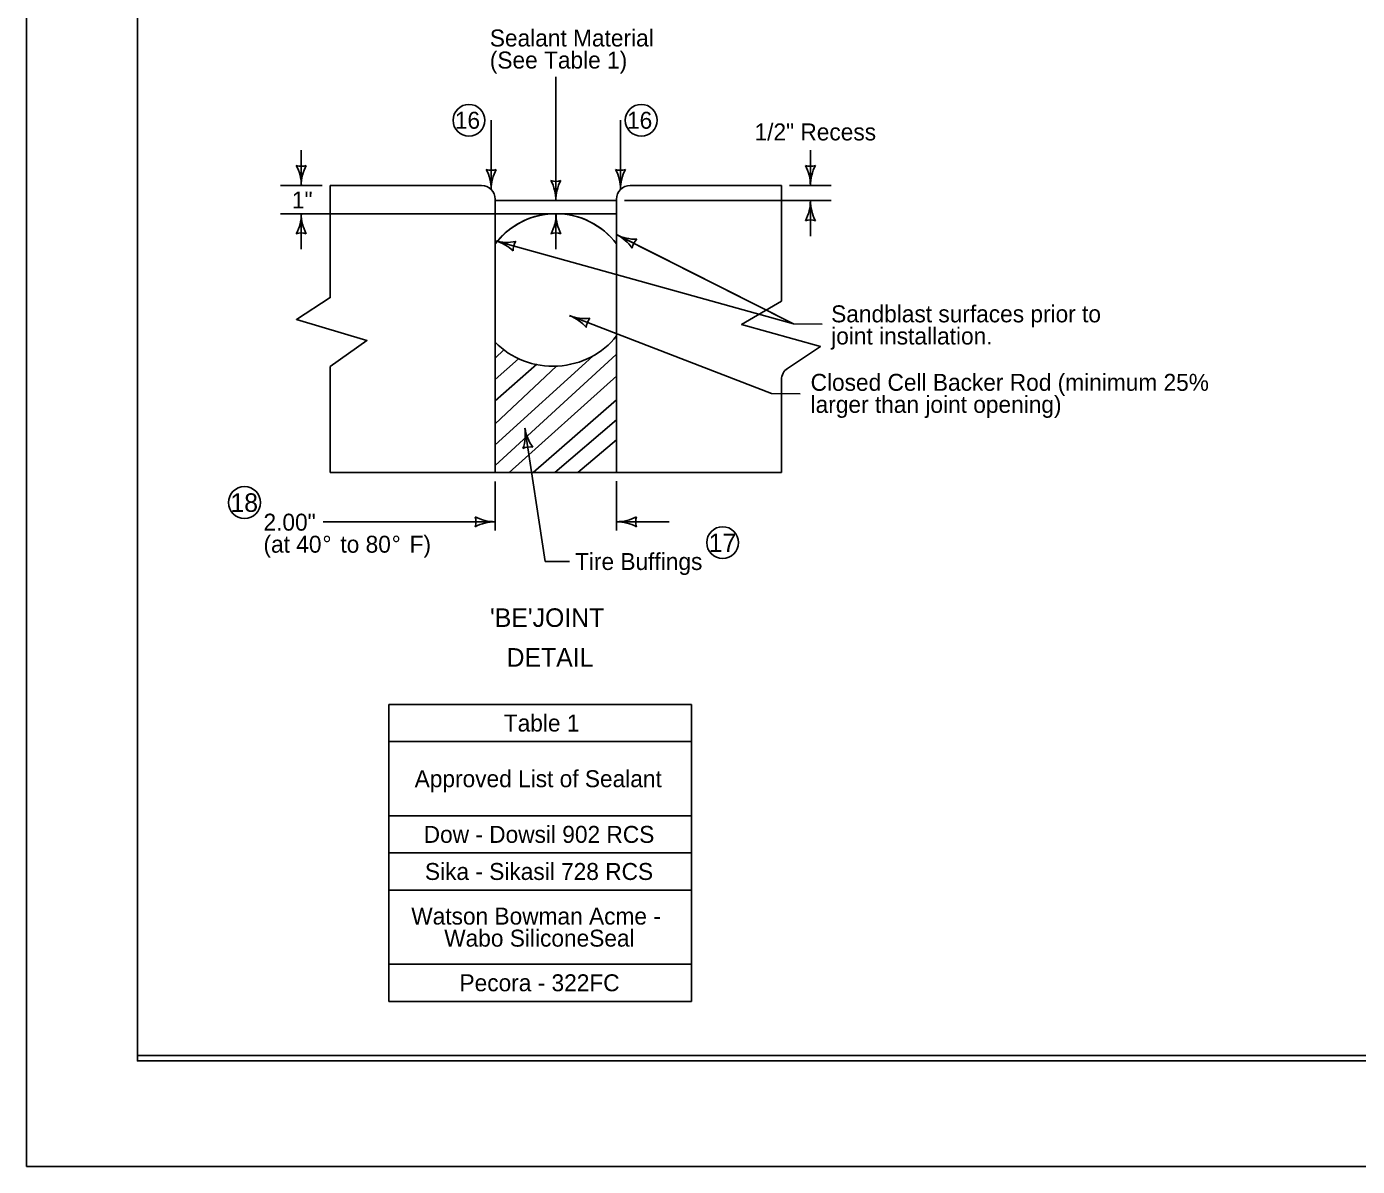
# Model space of a CAD drawing. Extents: x 10028 to 81668, y 6395 to 11634.
# Drawn here: x 24428 to 25683, y 7825 to 8900 of the extents above; entities that cross this region are included whole.
import ezdxf

# ---------------------------------------------------------------- set-up
doc = ezdxf.new("R2010")
doc.units = 0
for name, color, linetype in [('Default', 7, 'Continuous'), ('dsnCellElements', 7, 'Continuous'), ('dsnPaintPlaceStopLineWhite', 7, 'Continuous'), ('dsnstdblockInterim', 7, 'Continuous'), ('dsnStdDimension', 7, 'Continuous'), ('ShtPlotIdentification', 7, 'Continuous')]:
    doc.layers.add(name, color=color, linetype=linetype)

msp = doc.modelspace()

# ---------------------------------------------------------------- linework, layer by layer
at = {"layer": 'Default'}
for p, q in [((24714.4, 8644.1), (24714.4, 8749.7)), ((24714.4, 8749.7), (24857.3, 8749.7)), ((24870.1, 8736.9), (24870.1, 8735.5)), ((24870.1, 8706.9), (24870.1, 8735.5)), ((24870.1, 8735.5), (24870.1, 8479.2)), ((24870.1, 8735.5), (24984.5, 8735.5)), ((24984.5, 8479.2), (24984.5, 8736.9)), ((24984.5, 8735.5), (24984.5, 8700.8)), ((24984.5, 8735.5), (24984.5, 8723.2)), ((24984.5, 8723.2), (24870.1, 8723.2)), ((24870.1, 8723.2), (24870.1, 8694.6)), ((24870.1, 8694.6), (24870.1, 8723.2)), ((24926.9, 8723.2), (24927.7, 8723.2)), ((24984.5, 8694.6), (24984.5, 8723.2)), ((24984.5, 8723.2), (24984.5, 8694.6)), ((24984.1, 8703.7), (25151.4, 8619.3)), ((24682.6, 8623.3), (24714.4, 8644.1)), ((24749.1, 8603.5), (24682.6, 8623.3)), ((24714.4, 8578.9), (24749.1, 8603.5)), ((24869.9, 8586.9), (24878.1, 8594.9)), ((24870, 8505), (24962.1, 8588.9)), ((24870.1, 8485.5), (24984.3, 8590.2)), ((24714.4, 8479.2), (24714.4, 8578.9)), ((24869.9, 8566.8), (24892.1, 8586.4)), ((24869.9, 8525), (24927.9, 8579.5)), ((24870, 8546.5), (24909.2, 8581.2)), ((24883.4, 8479.2), (24984.7, 8570.1)), ((25140.1, 8479.2), (25140.1, 8566.6)), ((24906, 8479.1), (24984.5, 8547.7)), ((24926.3, 8479.1), (24984.5, 8528.6)), ((24948.1, 8479.2), (24984.6, 8510)), ((24984.5, 8479.2), (24714.4, 8479.2)), ((24984.5, 8479.2), (25140.1, 8479.2))]:
    msp.add_line(p, q, dxfattribs=at)
msp.add_lwpolyline([(24532.5, 9944), (27667.6, 9944), (27667.6, 7924), (24532.5, 7924)], close=True, dxfattribs=at)
for points in [[(25145.8, 8577.2), (25176.8, 8597.8), (25102.5, 8618.7), (25140, 8640.8), (25140.1, 8749.7), (24997.3, 8749.7)], [(24984.5, 8703.5), (24984.5, 8711.7), (24984.5, 8711.8), (24984.5, 8711.9), (24984.5, 8723.2), (24984.5, 8735.5), (24870.1, 8735.5), (24870.1, 8694.6)], [(24984.5, 8736.9), (24984.5, 8735.5), (24984.5, 8700.8), (24984.5, 8479.2), (24975.2, 8479.2)], [(24870.1, 8694.6), (24870.1, 8723.2), (24927.1, 8723.2)], [(24870.1, 8694.6), (24870.1, 8723.2), (24927.1, 8723.2)], [(24870.1, 8694.6), (24870.1, 8723.2), (24927.1, 8723.2)], [(24870.1, 8694.6), (24870.1, 8723.2), (24927.1, 8723.2)], [(24870.1, 8694.6), (24870.1, 8723.2), (24927.1, 8723.2)], [(24870.1, 8694.6), (24870.1, 8723.2), (24927.1, 8723.2)], [(24870.1, 8694.6), (24870.1, 8723.2), (24927.1, 8723.2)], [(24870.1, 8694.6), (24870.1, 8723.2), (24927.1, 8723.2)], [(24870.1, 8694.6), (24870.1, 8723.2), (24927.1, 8723.2)], [(24870.1, 8694.6), (24870.1, 8723.2), (24927.1, 8723.2)], [(24870.1, 8694.6), (24870.1, 8723.2), (24927.1, 8723.2)], [(24870.1, 8694.6), (24870.1, 8723.2), (24927.1, 8723.2)], [(24870.1, 8694.6), (24870.1, 8723.2), (24927.1, 8723.2)], [(24870.1, 8694.6), (24870.1, 8723.2), (24927.1, 8723.2)], [(24870.1, 8694.6), (24870.1, 8723.2), (24927.1, 8723.2)], [(24870.1, 8694.6), (24870.1, 8723.2), (24927.1, 8723.2)], [(24870.1, 8694.6), (24870.1, 8723.2), (24927.1, 8723.2)], [(24870.1, 8694.6), (24870.1, 8723.2), (24927.1, 8723.2)], [(24870.1, 8694.6), (24870.1, 8723.2), (24927.1, 8723.2)], [(24870.1, 8694.6), (24870.1, 8723.2), (24927.1, 8723.2)], [(24870.1, 8694.6), (24870.1, 8723.2), (24927.1, 8723.2)], [(24870.1, 8694.6), (24870.1, 8723.2), (24927.1, 8723.2)], [(24870.1, 8694.6), (24870.1, 8723.2), (24927.1, 8723.2)], [(24870.1, 8694.6), (24870.1, 8723.2), (24927.1, 8723.2)], [(24870.1, 8694.6), (24870.1, 8723.2), (24927.1, 8723.2)], [(24870.1, 8694.6), (24870.1, 8723.2), (24927.1, 8723.2)], [(24870.1, 8694.6), (24870.1, 8723.2), (24927.1, 8723.2)], [(24870.1, 8694.6), (24870.1, 8723.2), (24927.1, 8723.2)], [(24870.1, 8694.6), (24870.1, 8723.2), (24927.1, 8723.2)], [(24870.1, 8694.6), (24870.1, 8723.2), (24927.1, 8723.2)], [(24870.1, 8694.6), (24870.1, 8723.2), (24927.1, 8723.2)], [(24870.1, 8694.6), (24870.1, 8723.2), (24927.1, 8723.2)], [(24870.1, 8694.6), (24870.1, 8723.2), (24927.1, 8723.2)], [(24870.1, 8694.6), (24870.1, 8723.2), (24927.1, 8723.2)], [(24927.4, 8723.2), (24984.5, 8723.2), (24984.5, 8694.6)], [(24927.4, 8723.2), (24984.5, 8723.2), (24984.5, 8694.6)], [(24927.4, 8723.2), (24984.5, 8723.2), (24984.5, 8694.6)], [(24927.4, 8723.2), (24984.5, 8723.2), (24984.5, 8694.6)], [(24927.4, 8723.2), (24984.5, 8723.2), (24984.5, 8694.6)], [(24927.4, 8723.2), (24984.5, 8723.2), (24984.5, 8694.6)], [(24927.4, 8723.2), (24984.5, 8723.2), (24984.5, 8694.6)], [(24927.4, 8723.2), (24984.5, 8723.2), (24984.5, 8694.6)], [(24927.4, 8723.2), (24984.5, 8723.2), (24984.5, 8694.6)], [(24927.4, 8723.2), (24984.5, 8723.2), (24984.5, 8694.6)], [(24927.4, 8723.2), (24984.5, 8723.2), (24984.5, 8694.6)], [(24927.4, 8723.2), (24984.5, 8723.2), (24984.5, 8694.6)], [(24927.4, 8723.2), (24984.5, 8723.2), (24984.5, 8694.6)], [(24927.4, 8723.2), (24984.5, 8723.2), (24984.5, 8694.6)], [(24927.4, 8723.2), (24984.5, 8723.2), (24984.5, 8694.6)], [(24927.4, 8723.2), (24984.5, 8723.2), (24984.5, 8694.6)], [(24927.4, 8723.2), (24984.5, 8723.2), (24984.5, 8694.6)], [(24927.4, 8723.2), (24984.5, 8723.2), (24984.5, 8694.6)], [(24927.4, 8723.2), (24984.5, 8723.2), (24984.5, 8711.9), (24984.5, 8711.8), (24984.5, 8711.7), (24984.5, 8694.6)], [(24984.5, 8694.6), (24984.5, 8694.6), (24984.5, 8694.6), (24984.5, 8703.5)]]:
    msp.add_lwpolyline(points, dxfattribs=at)
for centre, radius, start, end in [((24857.3, 8736.9), 12.8, 0, 90), ((24997.3, 8736.9), 12.8, 90, 180), ((24927.3, 8651.7), 71.5, 36.8603, 143.1397), ((24927.3, 8651.7), 71.5, 90.1278, 143.139), ((24927.3, 8651.7), 71.5, 90.1278, 143.139), ((24927.3, 8651.7), 71.5, 90.1278, 143.1385), ((24927.3, 8651.7), 71.5, 90.1278, 143.1385), ((24927.3, 8651.7), 71.5, 90.1278, 143.1385), ((24927.3, 8651.7), 71.5, 90.1278, 143.1385), ((24927.3, 8651.7), 71.5, 90.1278, 143.1385), ((24927.3, 8651.7), 71.5, 90.1278, 143.1385), ((24927.3, 8651.7), 71.5, 90.1278, 143.1385), ((24927.3, 8651.7), 71.5, 90.1278, 143.1385), ((24927.3, 8651.7), 71.5, 90.1278, 143.1385), ((24927.3, 8651.7), 71.5, 90.1278, 143.1385), ((24927.3, 8651.7), 71.5, 90.1278, 143.1385), ((24927.3, 8651.7), 71.5, 90.1278, 143.1385), ((24927.3, 8651.7), 71.5, 90.1278, 143.1385), ((24927.3, 8651.7), 71.5, 90.1278, 143.1385), ((24927.3, 8651.7), 71.5, 90.1278, 143.1385), ((24927.3, 8651.7), 71.5, 90.1278, 143.1385), ((24927.3, 8651.7), 71.5, 90.1278, 143.1385), ((24927.3, 8651.7), 71.5, 90.1278, 143.1385), ((24927.3, 8651.7), 71.5, 90.1278, 143.1385), ((24927.3, 8651.7), 71.5, 90.1278, 143.1385), ((24927.3, 8651.7), 71.5, 90.1278, 143.1385), ((24927.3, 8651.7), 71.5, 90.1278, 143.1385), ((24927.3, 8651.7), 71.5, 90.1278, 143.1385), ((24927.3, 8651.7), 71.5, 90.1278, 143.1385), ((24927.3, 8651.7), 71.5, 90.1278, 143.1385), ((24927.3, 8651.7), 71.5, 90.1278, 143.1385), ((24927.3, 8651.7), 71.5, 90.1278, 143.1385), ((24927.3, 8651.7), 71.5, 90.1278, 143.1385), ((24927.3, 8651.7), 71.5, 90.1278, 143.1385), ((24927.3, 8651.7), 71.5, 90.1278, 143.1385), ((24927.3, 8651.7), 71.5, 90.1278, 143.1385), ((24927.3, 8651.7), 71.5, 98.1344, 143.1385), ((24927.3, 8651.7), 71.5, 90.3158, 140.4626), ((24927.3, 8651.7), 71.5, 90.1278, 98.1344), ((24927.3, 8651.7), 71.5, 36.8603, 89.8704), ((24927.3, 8651.7), 71.5, 36.8603, 89.8704), ((24927.3, 8651.7), 71.5, 36.8603, 89.8704), ((24927.3, 8651.7), 71.5, 36.8603, 89.8704), ((24927.3, 8651.7), 71.5, 36.8603, 89.8704), ((24927.3, 8651.7), 71.5, 36.8603, 89.8704), ((24927.3, 8651.7), 71.5, 36.8603, 89.8704), ((24927.3, 8651.7), 71.5, 36.8603, 89.8704), ((24927.3, 8651.7), 71.5, 36.8603, 89.8704), ((24927.3, 8651.7), 71.5, 36.8603, 89.8704), ((24927.3, 8651.7), 71.5, 36.8603, 89.8704), ((24927.3, 8651.7), 71.5, 36.8603, 89.8704), ((24927.3, 8651.7), 71.5, 36.8603, 89.8704), ((24927.3, 8651.7), 71.5, 36.8603, 89.8704), ((24927.3, 8651.7), 71.5, 36.8603, 89.8704), ((24927.3, 8651.7), 71.5, 36.8603, 89.8704), ((24927.3, 8651.7), 71.5, 36.8603, 89.8704), ((24927.3, 8651.7), 71.5, 36.8603, 89.8704), ((24927.3, 8651.7), 71.5, 36.8603, 89.8704), ((24927.3, 8651.7), 71.5, 36.8603, 89.6842), ((24966, 8667.8), 40.2, 62.5774, 63.2482), ((25002.2, 8739.6), 40.2, 243.2482, 243.9147), ((24927.3, 8651.7), 71.5, 140.4626, 143.1385), ((25152.9, 8566.6), 12.8, 123.5371, 180), ((25152.9, 8566.6), 12.8, 123.5371, 180)]:
    msp.add_arc(centre, radius, start, end, dxfattribs=at)
for centre, start_param, end_param in [((24924.7, 8656.5), 0.606648, 0.606655), ((24924.7, 8646.1), 3.864857, 5.676062)]:
    msp.add_ellipse(centre, major_axis=(72.8, 0), ratio=0.91682, start_param=start_param, end_param=end_param, dxfattribs=at)
at = {"layer": 'dsnCellElements'}
for p, q in [((24927.3, 8735.5), (24927.3, 8852.4)), ((24866.3, 8746), (24866.3, 8811.5)), ((24988.2, 8746), (24988.2, 8811.5)), ((24687.1, 8749.7), (24687.1, 8783.2)), ((25167.4, 8749.7), (25167.4, 8783.2)), ((24706.9, 8749.7), (24667.4, 8749.7)), ((25187.1, 8749.7), (25147.7, 8749.7)), ((24992.1, 8735.5), (25187.1, 8735.5)), ((25167.4, 8702), (25167.4, 8735.5)), ((24902.5, 8723.2), (24667.4, 8723.2)), ((24687.1, 8689.6), (24687.1, 8723.2)), ((24927.4, 8689.6), (24927.4, 8723.2)), ((25151.4, 8619.3), (24984.5, 8703.5)), ((24870, 8697.6), (25151.4, 8619.3)), ((25130.7, 8553.6), (24940.1, 8627)), ((25151.4, 8619.3), (25178.4, 8619.1)), ((25130.7, 8553.6), (25157.7, 8553.4)), ((24917.2, 8395.1), (24898, 8521)), ((24870.1, 8470.7), (24870.1, 8424.3)), ((24984.5, 8470.9), (24984.5, 8424.3)), ((24870.1, 8432.6), (24707.8, 8432.6)), ((24984.5, 8432.6), (25034.1, 8432.6)), ((24940.2, 8395.1), (24917.2, 8395.1))]:
    msp.add_line(p, q, dxfattribs=at)
at = {"layer": 'dsnstdblockInterim'}
msp.add_lwpolyline([(24532.5, 9939), (27667.5, 9939), (27667.5, 7929), (24532.5, 7929)], close=True, dxfattribs=at)
at = {"layer": 'dsnStdDimension'}
msp.add_lwpolyline([(24428, 7824.5), (27772, 7824.5), (27772, 10408.5), (24428, 10408.5)], close=True, dxfattribs=at)
at = {"layer": 'ShtPlotIdentification'}
for p, q in [((24769.8, 8260.2), (24769.8, 7980.2)), ((24769.8, 8260.2), (25055.2, 8260.2)), ((25055.2, 8260.2), (25055.2, 7980.2)), ((24769.8, 8225.2), (25055.2, 8225.2)), ((24769.8, 8155.2), (25055.2, 8155.2)), ((24769.8, 8120.2), (25055.2, 8120.2)), ((24769.8, 8085.2), (25055.2, 8085.2)), ((24769.8, 8015.2), (25055.2, 8015.2)), ((24769.8, 7980.2), (25055.2, 7980.2))]:
    msp.add_line(p, q, dxfattribs=at)
for points in [[(24857.3, 8749.7), (24714.4, 8749.7), (24714.4, 8644.1), (24682.6, 8623.3), (24749.1, 8603.5), (24714.4, 8578.9), (24714.4, 8479.2), (24870.1, 8479.2), (24870.1, 8694.6)], [(25145.8, 8577.2), (25176.8, 8597.8), (25102.5, 8618.7), (25140, 8640.8), (25140.1, 8749.7), (24997.3, 8749.7)], [(24870.1, 8694.6), (24870.1, 8697.6), (24870.1, 8723.2), (24870.1, 8735.5), (24870.1, 8736.9)], [(24984.5, 8736.9), (24984.5, 8735.5), (24984.5, 8735.5), (24984.5, 8729.2), (24984.5, 8703.5), (24984.5, 8700.8), (24984.5, 8479.2), (25140.1, 8479.2), (25140.1, 8566.6)]]:
    msp.add_lwpolyline(points, dxfattribs=at)
for centre in [(24845.3, 8811.3), (25007.8, 8811.3), (24633.6, 8450.7), (25084.6, 8412.9)]:
    msp.add_circle(centre, 15, dxfattribs=at)
for centre, radius, start, end in [((24687.1, 8783.4), 15.5, 252.2666, 287.7333), ((24647, 8749.7), 40.2, 360, 28.0725), ((24727.3, 8749.7), 40.2, 151.9275, 180), ((24866.3, 8779.6), 15.5, 252.2666, 287.7333), ((24826.1, 8746), 40.2, 360, 28.0725), ((24906.5, 8746), 40.2, 151.9275, 180), ((24988.2, 8779.6), 15.5, 252.2666, 287.7333), ((24948.1, 8746), 40.2, 360, 28.0725), ((25028.4, 8746), 40.2, 151.9275, 180), ((25167.4, 8783.4), 15.5, 252.2666, 287.7333), ((25127.2, 8749.7), 40.2, 360, 28.0725), ((25207.6, 8749.7), 40.2, 151.9275, 180), ((24857.3, 8736.9), 12.8, 0, 90), ((24927.3, 8769.2), 15.5, 252.2666, 287.7333), ((24887.1, 8735.5), 40.2, 360, 28.0725), ((24967.4, 8735.5), 40.2, 151.9275, 180), ((24997.3, 8736.9), 12.8, 90, 180), ((25127.2, 8735.5), 40.2, 331.9275, 0), ((25207.6, 8735.5), 40.2, 180, 208.0725), ((24647, 8723.2), 40.2, 331.9275, 0), ((24727.3, 8723.2), 40.2, 180, 208.0725), ((24887.3, 8723.2), 40.2, 331.9275, 0), ((24967.6, 8723.2), 40.2, 180, 208.0725), ((25167.4, 8701.8), 15.5, 72.2667, 107.7334), ((24687.1, 8689.5), 15.5, 72.2667, 107.7334), ((24927.4, 8689.5), 15.5, 72.2667, 107.7334), ((24966.4, 8667.6), 40.2, 35.1757, 63.2482), ((25002.6, 8739.3), 40.2, 243.2482, 271.3206), ((24859.3, 8658.9), 40.2, 46.3768, 74.4493), ((24880.8, 8736.3), 40.2, 254.4493, 282.5218), ((24927.3, 8651.7), 71.5, 143.1385, 143.139), ((24902.5, 8688.6), 15.5, 146.716, 182.1827), ((25014.6, 8688.3), 15.5, 135.5148, 170.9815), ((24925.7, 8589.5), 40.2, 40.8833, 68.9558), ((24954.5, 8664.5), 40.2, 248.9558, 277.0283), ((24971.5, 8614.9), 15.5, 141.2225, 176.6892), ((25152.9, 8566.6), 12.8, 123.5371, 179.992), ((25152.9, 8566.6), 12.8, 179.992, 180), ((24858.3, 8514.9), 40.2, 340.591, 8.6635), ((24937.8, 8527), 40.2, 188.6635, 216.7359), ((24903.1, 8487.7), 15.5, 80.9301, 116.3968), ((24836.4, 8432.6), 15.5, 342.2666, 17.7333), ((24870.1, 8472.8), 40.2, 241.9275, 270), ((24984.5, 8472.8), 40.2, 270, 298.0725), ((25018.2, 8432.6), 15.5, 162.2666, 197.7333), ((24870.1, 8392.4), 40.2, 90, 118.0725), ((24984.5, 8392.4), 40.2, 61.9275, 90)]:
    msp.add_arc(centre, radius, start, end, dxfattribs=at)

# ---------------------------------------------------------------- texts
at = {"layer": 'dsnCellElements'}
for s, height, p in [('Sealant Material', 16, (24865, 8880.9)), ('(See Table 1)', 16, (24865, 8860.1)), ('1/2" Recess', 16, (25114.7, 8792.3)), ('1"', 16, (24678.3, 8728.1)), ('Sandblast surfaces prior to ', 16, (25187, 8620.7)), ('joint installation.', 16, (25187, 8599.8)), ('Closed Cell Backer Rod (minimum 25%', 16, (25167.6, 8556.1)), ('larger than joint opening)', 16, (25167.6, 8535.3)), ('18', 17.5, (24620.3, 8441.9)), ('2.00"', 16, (24651.5, 8424.2)), ('(at 40', 16, (24651.5, 8403.4)), ('°', 16, (24707.1, 8403.4)), (' to 80', 16, (24718.1, 8403.4)), ('°', 16, (24772.4, 8403.4)), (' F)', 16, (24783.4, 8403.4)), ('17', 17.5, (25071.5, 8404)), ('Tire Buffings', 16, (24945.4, 8387.1)), ('Table 1', 16, (24878.2, 8234.7)), ('Approved List of Sealant', 16, (24794.1, 8182.2)), ('Dow - Dowsil 902 RCS', 16, (24802.6, 8129.7)), ('Sika - Sikasil 728 RCS', 16, (24803.8, 8094.7)), ('Watson Bowman Acme - ', 16, (24790.9, 8052.6)), ('Wabo SiliconeSeal', 16, (24822, 8031.8)), ('Pecora - 322FC', 16, (24836.4, 7989.7))]:
    msp.add_text(s, height=height, dxfattribs=at).set_placement(p)
at = {"layer": 'dsnPaintPlaceStopLineWhite'}
for p in [(24832, 8803.3), (24994.4, 8803.3)]:
    msp.add_text('16', height=16, dxfattribs=at).set_placement(p)
at = {"layer": 'ShtPlotIdentification'}
for s, p in [("   'BE'JOINT ", (24845.7, 8333.4)), ('   DETAIL', (24861.3, 8295.9))]:
    msp.add_text(s, height=17.5, dxfattribs=at).set_placement(p)

doc.saveas('drawing.dxf')
